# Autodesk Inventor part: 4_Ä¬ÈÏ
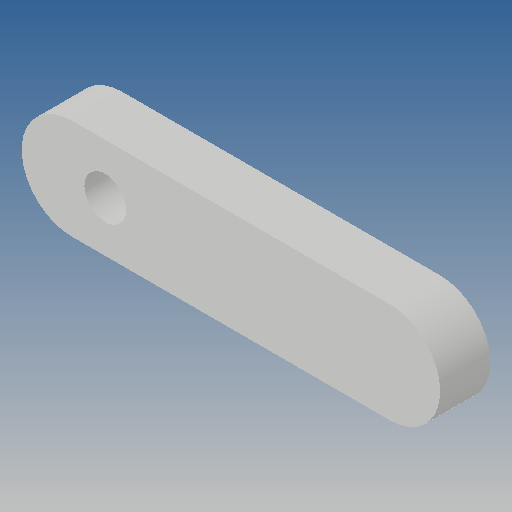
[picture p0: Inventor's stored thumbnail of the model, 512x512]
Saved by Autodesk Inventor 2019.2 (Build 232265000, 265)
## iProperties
Created: 2010-06
Part Number: 4_Ä¬ÈÏ
Material: Ogólny
Document SubType Name: Modeling
Designer: CADENGINEERING4
Density: 1 g/cm^3
Appearance: Domyślna
Author: CADENGINEERING4
Revision Number: ÈÎºÎ
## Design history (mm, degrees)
feature "NONE"
node "Bryła1"
